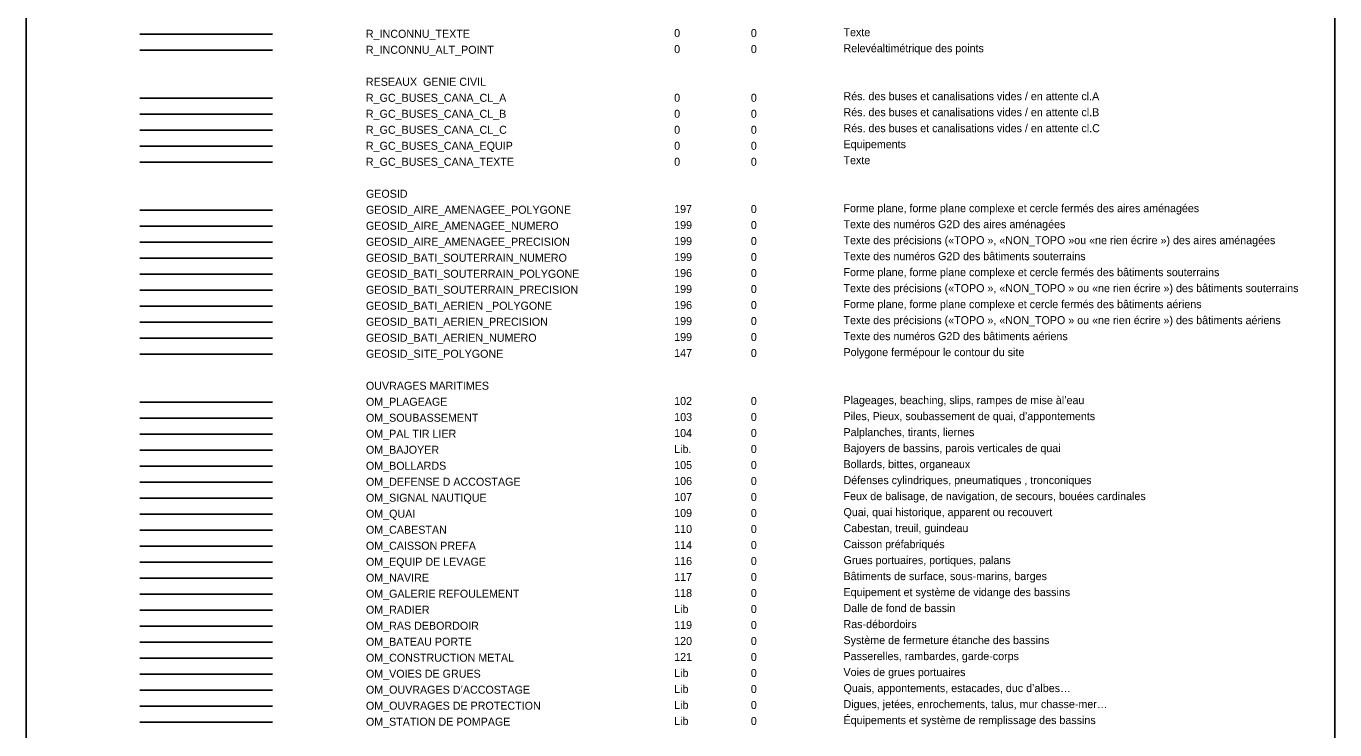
# Model space of a CAD drawing. Extents: x -60 to 214, y -380 to -21.
# Drawn here: x 33.1 to 114.8, y -334.9 to -290.9 of the extents above; entities that cross this region are included whole.
import ezdxf

# ---------------------------------------------------------------- set-up
doc = ezdxf.new("R2010")
doc.units = 0
for name, color, linetype in [('Default', 7, 'Continuous'), ('DH_TEXTE', 7, 'Continuous'), ('GEOSID_AIRE_AMENAGEE_NUMERO', 7, 'Continuous'), ('GEOSID_AIRE_AMENAGEE_POLYGONE', 7, 'Continuous'), ('GEOSID_AIRE_AMENAGEE_PRECISION', 7, 'Continuous'), ('GEOSID_BATI_AERIEN _POLYGONE', 7, 'Continuous'), ('GEOSID_BATI_AERIEN_NUMERO', 7, 'Continuous'), ('GEOSID_BATI_AERIEN_PRECISION', 7, 'Continuous'), ('GEOSID_BATI_SOUTERRAIN_NUMERO', 7, 'Continuous'), ('GEOSID_BATI_SOUTERRAIN_POLYGONE', 7, 'Continuous'), ('GEOSID_BATI_SOUTERRAIN_PRECISION', 7, 'Continuous'), ('GEOSID_SITE_POLYGONE', 7, 'Continuous'), ('OM_BAJOYER', 7, 'Continuous'), ('OM_BATEAU PORTE', 7, 'Continuous'), ('OM_BOLLARDS', 7, 'Continuous'), ('OM_CABESTAN', 7, 'Continuous'), ('OM_CAISSON PREFA', 7, 'Continuous'), ('OM_CONSTRUCTION METAL', 7, 'Continuous'), ('OM_DEFENSE D ACCOSTAGE', 7, 'Continuous'), ('OM_EQUIP DE LEVAGE', 7, 'Continuous'), ('OM_GALERIE REFOULEMENT', 7, 'Continuous'), ('OM_NAVIRE', 7, 'Continuous'), ('OM_OUVRAGES DE PROTECTION', 7, 'Continuous'), ('OM_OUVRAGES D’ACCOSTAGE', 7, 'Continuous'), ('OM_PAL TIR LIER', 7, 'Continuous'), ('OM_PLAGEAGE', 7, 'Continuous'), ('OM_QUAI', 7, 'Continuous'), ('OM_RADIER', 7, 'Continuous'), ('OM_RAS DEBORDOIR', 7, 'Continuous'), ('OM_SIGNAL NAUTIQUE', 7, 'Continuous'), ('OM_SOUBASSEMENT', 7, 'Continuous'), ('OM_STATION DE POMPAGE', 7, 'Continuous'), ('OM_VOIES DE GRUES', 7, 'Continuous'), ('R_GC_BUSES_CANA_CL_A', 7, 'Continuous'), ('R_GC_BUSES_CANA_CL_B', 7, 'Continuous'), ('R_GC_BUSES_CANA_CL_C', 7, 'Continuous'), ('R_GC_BUSES_CANA_EQUIP', 7, 'Continuous'), ('R_GC_BUSES_CANA_TEXTE', 7, 'Continuous'), ('R_INCONNU_ALT_POINT', 7, 'Continuous'), ('R_INCONNU_TEXTE', 7, 'Continuous')]:
    doc.layers.add(name, color=color, linetype=linetype)

msp = doc.modelspace()

# ---------------------------------------------------------------- linework, layer by layer
at = {"layer": 'Default'}
msp.add_lwpolyline([(114.838, -25.727), (33.073, -25.727), (33.073, -380.216), (114.838, -380.216)], close=True, dxfattribs=at)
at = {"layer": 'GEOSID_AIRE_AMENAGEE_NUMERO'}
msp.add_line((40.178, -303.429), (48.457, -303.429), dxfattribs=at)
at = {"layer": 'GEOSID_AIRE_AMENAGEE_POLYGONE'}
msp.add_line((40.178, -302.429), (48.457, -302.429), dxfattribs=at)
at = {"layer": 'GEOSID_AIRE_AMENAGEE_PRECISION'}
msp.add_line((40.178, -304.429), (48.457, -304.429), dxfattribs=at)
at = {"layer": 'GEOSID_BATI_AERIEN _POLYGONE'}
msp.add_line((40.178, -308.429), (48.457, -308.429), dxfattribs=at)
at = {"layer": 'GEOSID_BATI_AERIEN_NUMERO'}
msp.add_line((40.178, -310.429), (48.457, -310.429), dxfattribs=at)
at = {"layer": 'GEOSID_BATI_AERIEN_PRECISION'}
msp.add_line((40.178, -309.429), (48.457, -309.429), dxfattribs=at)
at = {"layer": 'GEOSID_BATI_SOUTERRAIN_NUMERO'}
msp.add_line((40.178, -305.429), (48.457, -305.429), dxfattribs=at)
at = {"layer": 'GEOSID_BATI_SOUTERRAIN_POLYGONE'}
msp.add_line((40.178, -306.429), (48.457, -306.429), dxfattribs=at)
at = {"layer": 'GEOSID_BATI_SOUTERRAIN_PRECISION'}
msp.add_line((40.178, -307.429), (48.457, -307.429), dxfattribs=at)
at = {"layer": 'GEOSID_SITE_POLYGONE'}
msp.add_line((40.178, -311.429), (48.457, -311.429), dxfattribs=at)
at = {"layer": 'OM_BAJOYER'}
msp.add_line((40.178, -317.429), (48.457, -317.429), dxfattribs=at)
at = {"layer": 'OM_BATEAU PORTE'}
msp.add_line((40.178, -329.429), (48.457, -329.429), dxfattribs=at)
at = {"layer": 'OM_BOLLARDS'}
msp.add_line((40.178, -318.429), (48.457, -318.429), dxfattribs=at)
at = {"layer": 'OM_CABESTAN'}
msp.add_line((40.178, -322.429), (48.457, -322.429), dxfattribs=at)
at = {"layer": 'OM_CAISSON PREFA'}
msp.add_line((40.178, -323.429), (48.457, -323.429), dxfattribs=at)
at = {"layer": 'OM_CONSTRUCTION METAL'}
msp.add_line((40.178, -330.429), (48.457, -330.429), dxfattribs=at)
at = {"layer": 'OM_DEFENSE D ACCOSTAGE'}
msp.add_line((40.178, -319.429), (48.457, -319.429), dxfattribs=at)
at = {"layer": 'OM_EQUIP DE LEVAGE'}
msp.add_line((40.178, -324.429), (48.457, -324.429), dxfattribs=at)
at = {"layer": 'OM_GALERIE REFOULEMENT'}
msp.add_line((40.178, -326.429), (48.457, -326.429), dxfattribs=at)
at = {"layer": 'OM_NAVIRE'}
msp.add_line((40.178, -325.429), (48.457, -325.429), dxfattribs=at)
at = {"layer": 'OM_OUVRAGES DE PROTECTION'}
msp.add_line((40.178, -333.429), (48.457, -333.429), dxfattribs=at)
at = {"layer": 'OM_OUVRAGES D’ACCOSTAGE'}
msp.add_line((40.178, -332.429), (48.457, -332.429), dxfattribs=at)
at = {"layer": 'OM_PAL TIR LIER'}
msp.add_line((40.178, -316.429), (48.457, -316.429), dxfattribs=at)
at = {"layer": 'OM_PLAGEAGE'}
msp.add_line((40.178, -314.429), (48.457, -314.429), dxfattribs=at)
at = {"layer": 'OM_QUAI'}
msp.add_line((40.178, -321.429), (48.457, -321.429), dxfattribs=at)
at = {"layer": 'OM_RADIER'}
msp.add_line((40.178, -327.429), (48.457, -327.429), dxfattribs=at)
at = {"layer": 'OM_RAS DEBORDOIR'}
msp.add_line((40.178, -328.429), (48.457, -328.429), dxfattribs=at)
at = {"layer": 'OM_SIGNAL NAUTIQUE'}
msp.add_line((40.178, -320.429), (48.457, -320.429), dxfattribs=at)
at = {"layer": 'OM_SOUBASSEMENT'}
msp.add_line((40.178, -315.429), (48.457, -315.429), dxfattribs=at)
at = {"layer": 'OM_STATION DE POMPAGE'}
msp.add_line((40.178, -334.429), (48.457, -334.429), dxfattribs=at)
at = {"layer": 'OM_VOIES DE GRUES'}
msp.add_line((40.178, -331.429), (48.457, -331.429), dxfattribs=at)
at = {"layer": 'R_GC_BUSES_CANA_CL_A'}
msp.add_line((40.178, -295.429), (48.457, -295.429), dxfattribs=at)
at = {"layer": 'R_GC_BUSES_CANA_CL_B'}
msp.add_line((40.178, -296.429), (48.457, -296.429), dxfattribs=at)
at = {"layer": 'R_GC_BUSES_CANA_CL_C'}
msp.add_line((40.178, -297.429), (48.457, -297.429), dxfattribs=at)
at = {"layer": 'R_GC_BUSES_CANA_EQUIP'}
msp.add_line((40.178, -298.429), (48.457, -298.429), dxfattribs=at)
at = {"layer": 'R_GC_BUSES_CANA_TEXTE'}
msp.add_line((40.178, -299.429), (48.457, -299.429), dxfattribs=at)
at = {"layer": 'R_INCONNU_ALT_POINT'}
msp.add_line((40.178, -292.429), (48.457, -292.429), dxfattribs=at)
at = {"layer": 'R_INCONNU_TEXTE'}
msp.add_line((40.178, -291.429), (48.457, -291.429), dxfattribs=at)

# ---------------------------------------------------------------- texts
at = {"layer": 'DH_TEXTE'}
for s, p in [('RESEAUX  GENIE CIVIL', (54.301, -294.655)), ('GEOSID ', (54.301, -301.655)), ('OUVRAGES MARITIMES ', (54.301, -313.655))]:
    msp.add_text(s, height=0.5, dxfattribs=at).set_placement(p)
at = {"layer": 'GEOSID_AIRE_AMENAGEE_NUMERO'}
for s, p in [('GEOSID_AIRE_AMENAGEE_NUMERO ', (54.301, -303.655)), ('199 ', (73.561, -303.61)), ('0 ', (78.351, -303.61)), ('Texte des numéros G2D des aires aménagées ', (84.14, -303.555))]:
    msp.add_text(s, height=0.5, dxfattribs=at).set_placement(p)
at = {"layer": 'GEOSID_AIRE_AMENAGEE_POLYGONE'}
for s, p in [('GEOSID_AIRE_AMENAGEE_POLYGONE ', (54.301, -302.655)), ('197 ', (73.559, -302.61)), ('0 ', (78.348, -302.61)), ('Forme plane, forme plane complexe et cercle fermés des aires aménagées ', (84.138, -302.555))]:
    msp.add_text(s, height=0.5, dxfattribs=at).set_placement(p)
at = {"layer": 'GEOSID_AIRE_AMENAGEE_PRECISION'}
for s, p in [('GEOSID_AIRE_AMENAGEE_PRECISION ', (54.301, -304.655)), ('199 ', (73.561, -304.61)), ('0 ', (78.351, -304.61)), ('Texte des précisions («TOPO », «NON_TOPO »ou «ne rien écrire ») des aires aménagées ', (84.14, -304.555))]:
    msp.add_text(s, height=0.5, dxfattribs=at).set_placement(p)
at = {"layer": 'GEOSID_BATI_AERIEN _POLYGONE'}
for s, p in [('GEOSID_BATI_AERIEN _POLYGONE ', (54.301, -308.655)), ('196 ', (73.561, -308.61)), ('0 ', (78.351, -308.61)), ('Forme plane, forme plane complexe et cercle fermés des bâtiments aériens ', (84.14, -308.555))]:
    msp.add_text(s, height=0.5, dxfattribs=at).set_placement(p)
at = {"layer": 'GEOSID_BATI_AERIEN_NUMERO'}
for s, p in [('GEOSID_BATI_AERIEN_NUMERO ', (54.301, -310.655)), ('199 ', (73.561, -310.61)), ('0 ', (78.351, -310.61)), ('Texte des numéros G2D des bâtiments aériens ', (84.14, -310.555))]:
    msp.add_text(s, height=0.5, dxfattribs=at).set_placement(p)
at = {"layer": 'GEOSID_BATI_AERIEN_PRECISION'}
for s, p in [('Texte des précisions («TOPO », «NON_TOPO » ou «ne rien écrire ») des bâtiments aériens ', (84.14, -309.555)), ('GEOSID_BATI_AERIEN_PRECISION ', (54.301, -309.655)), ('199 ', (73.561, -309.61)), ('0 ', (78.351, -309.61))]:
    msp.add_text(s, height=0.5, dxfattribs=at).set_placement(p)
at = {"layer": 'GEOSID_BATI_SOUTERRAIN_NUMERO'}
for s, p in [('GEOSID_BATI_SOUTERRAIN_NUMERO ', (54.301, -305.655)), ('199 ', (73.561, -305.61)), ('0 ', (78.351, -305.61)), ('Texte des numéros G2D des bâtiments souterrains ', (84.14, -305.555))]:
    msp.add_text(s, height=0.5, dxfattribs=at).set_placement(p)
at = {"layer": 'GEOSID_BATI_SOUTERRAIN_POLYGONE'}
for s, p in [('GEOSID_BATI_SOUTERRAIN_POLYGONE ', (54.301, -306.655)), ('196 ', (73.561, -306.61)), ('0 ', (78.351, -306.61)), ('Forme plane, forme plane complexe et cercle fermés des bâtiments souterrains ', (84.14, -306.555))]:
    msp.add_text(s, height=0.5, dxfattribs=at).set_placement(p)
at = {"layer": 'GEOSID_BATI_SOUTERRAIN_PRECISION'}
for s, p in [('GEOSID_BATI_SOUTERRAIN_PRECISION ', (54.301, -307.655)), ('199 ', (73.561, -307.61)), ('0 ', (78.351, -307.61)), ('Texte des précisions («TOPO », «NON_TOPO » ou «ne rien écrire ») des bâtiments souterrains ', (84.14, -307.555))]:
    msp.add_text(s, height=0.5, dxfattribs=at).set_placement(p)
at = {"layer": 'GEOSID_SITE_POLYGONE'}
for s, p in [('GEOSID_SITE_POLYGONE ', (54.301, -311.655)), ('147 ', (73.561, -311.61)), ('0 ', (78.351, -311.61)), ('Polygone fermépour le contour du site ', (84.14, -311.555))]:
    msp.add_text(s, height=0.5, dxfattribs=at).set_placement(p)
at = {"layer": 'OM_BAJOYER'}
for s, p in [('OM_BAJOYER ', (54.301, -317.655)), ('Lib. ', (73.561, -317.61)), ('0', (78.348, -317.61)), ('Bajoyers de bassins, parois verticales de quai ', (84.14, -317.555))]:
    msp.add_text(s, height=0.5, dxfattribs=at).set_placement(p)
at = {"layer": 'OM_BATEAU PORTE'}
for s, p in [('OM_BATEAU PORTE ', (54.301, -329.655)), ('120 ', (73.561, -329.61)), ('0', (78.348, -329.61)), ('Système de fermeture étanche des bassins ', (84.14, -329.555))]:
    msp.add_text(s, height=0.5, dxfattribs=at).set_placement(p)
at = {"layer": 'OM_BOLLARDS'}
for s, p in [('Bollards, bittes, organeaux ', (84.14, -318.555)), ('OM_BOLLARDS ', (54.301, -318.655)), ('105 ', (73.561, -318.61)), ('0', (78.348, -318.61))]:
    msp.add_text(s, height=0.5, dxfattribs=at).set_placement(p)
at = {"layer": 'OM_CABESTAN'}
for s, p in [('OM_CABESTAN ', (54.301, -322.655)), ('110 ', (73.561, -322.61)), ('0', (78.348, -322.61)), ('Cabestan, treuil, guindeau ', (84.14, -322.555))]:
    msp.add_text(s, height=0.5, dxfattribs=at).set_placement(p)
at = {"layer": 'OM_CAISSON PREFA'}
for s, p in [('OM_CAISSON PREFA ', (54.301, -323.655)), ('114 ', (73.561, -323.61)), ('0', (78.348, -323.61)), ('Caisson préfabriqués ', (84.14, -323.555))]:
    msp.add_text(s, height=0.5, dxfattribs=at).set_placement(p)
at = {"layer": 'OM_CONSTRUCTION METAL'}
for s, p in [('OM_CONSTRUCTION METAL ', (54.301, -330.655)), ('121 ', (73.561, -330.61)), ('0', (78.348, -330.61)), ('Passerelles, rambardes, garde-corps ', (84.14, -330.555))]:
    msp.add_text(s, height=0.5, dxfattribs=at).set_placement(p)
at = {"layer": 'OM_DEFENSE D ACCOSTAGE'}
for s, p in [('OM_DEFENSE D ACCOSTAGE ', (54.301, -319.655)), ('106 ', (73.561, -319.61)), ('0', (78.348, -319.61)), ('Défenses cylindriques, pneumatiques , tronconiques ', (84.14, -319.555))]:
    msp.add_text(s, height=0.5, dxfattribs=at).set_placement(p)
at = {"layer": 'OM_EQUIP DE LEVAGE'}
for s, p in [('OM_EQUIP DE LEVAGE ', (54.301, -324.655)), ('116 ', (73.561, -324.61)), ('0', (78.348, -324.61)), ('Grues portuaires, portiques, palans ', (84.14, -324.555))]:
    msp.add_text(s, height=0.5, dxfattribs=at).set_placement(p)
at = {"layer": 'OM_GALERIE REFOULEMENT'}
for s, p in [('OM_GALERIE REFOULEMENT ', (54.301, -326.655)), ('118 ', (73.561, -326.61)), ('0', (78.348, -326.61)), ('Equipement et système de vidange des bassins ', (84.14, -326.555))]:
    msp.add_text(s, height=0.5, dxfattribs=at).set_placement(p)
at = {"layer": 'OM_NAVIRE'}
for s, p in [('OM_NAVIRE ', (54.301, -325.655)), ('117 ', (73.561, -325.61)), ('0', (78.348, -325.61)), ('Bâtiments de surface, sous-marins, barges ', (84.14, -325.555))]:
    msp.add_text(s, height=0.5, dxfattribs=at).set_placement(p)
at = {"layer": 'OM_OUVRAGES DE PROTECTION'}
for s, p in [('OM_OUVRAGES DE PROTECTION ', (54.301, -333.655)), ('Lib ', (73.561, -333.61)), ('0', (78.348, -333.61)), ('Digues, jetées, enrochements, talus, mur chasse-mer…', (84.14, -333.555))]:
    msp.add_text(s, height=0.5, dxfattribs=at).set_placement(p)
at = {"layer": 'OM_OUVRAGES D’ACCOSTAGE'}
for s, p in [('OM_OUVRAGES D’ACCOSTAGE ', (54.301, -332.655)), ('Lib ', (73.561, -332.61)), ('0', (78.348, -332.61)), ('Quais, appontements, estacades, duc d’albes…', (84.14, -332.555))]:
    msp.add_text(s, height=0.5, dxfattribs=at).set_placement(p)
at = {"layer": 'OM_PAL TIR LIER'}
for s, p in [('OM_PAL TIR LIER ', (54.301, -316.655)), ('104 ', (73.561, -316.61)), ('0', (78.348, -316.61)), ('Palplanches, tirants, liernes ', (84.14, -316.555))]:
    msp.add_text(s, height=0.5, dxfattribs=at).set_placement(p)
at = {"layer": 'OM_PLAGEAGE'}
for s, p in [('OM_PLAGEAGE ', (54.301, -314.655)), ('102 ', (73.559, -314.61)), ('0', (78.348, -314.61)), ('Plageages, beaching, slips, rampes de mise àl’eau ', (84.138, -314.555))]:
    msp.add_text(s, height=0.5, dxfattribs=at).set_placement(p)
at = {"layer": 'OM_QUAI'}
for s, p in [('OM_QUAI ', (54.301, -321.655)), ('109 ', (73.561, -321.61)), ('0', (78.348, -321.61)), ('Quai, quai historique, apparent ou recouvert ', (84.14, -321.555))]:
    msp.add_text(s, height=0.5, dxfattribs=at).set_placement(p)
at = {"layer": 'OM_RADIER'}
for s, p in [('Dalle de fond de bassin ', (84.14, -327.555)), ('OM_RADIER ', (54.301, -327.655)), ('Lib ', (73.561, -327.61)), ('0', (78.348, -327.61))]:
    msp.add_text(s, height=0.5, dxfattribs=at).set_placement(p)
at = {"layer": 'OM_RAS DEBORDOIR'}
for s, p in [('OM_RAS DEBORDOIR ', (54.301, -328.655)), ('119 ', (73.561, -328.61)), ('0', (78.348, -328.61)), ('Ras-débordoirs ', (84.14, -328.555))]:
    msp.add_text(s, height=0.5, dxfattribs=at).set_placement(p)
at = {"layer": 'OM_SIGNAL NAUTIQUE'}
for s, p in [('OM_SIGNAL NAUTIQUE ', (54.301, -320.655)), ('107 ', (73.561, -320.61)), ('0', (78.348, -320.61)), ('Feux de balisage, de navigation, de secours, bouées cardinales ', (84.14, -320.555))]:
    msp.add_text(s, height=0.5, dxfattribs=at).set_placement(p)
at = {"layer": 'OM_SOUBASSEMENT'}
for s, p in [('OM_SOUBASSEMENT ', (54.301, -315.655)), ('103 ', (73.561, -315.61)), ('0', (78.348, -315.61)), ('Piles, Pieux, soubassement de quai, d’appontements ', (84.14, -315.555))]:
    msp.add_text(s, height=0.5, dxfattribs=at).set_placement(p)
at = {"layer": 'OM_STATION DE POMPAGE'}
for s, p in [('OM_STATION DE POMPAGE  ', (54.301, -334.655)), ('Lib ', (73.561, -334.61)), ('0', (78.348, -334.61)), ('Équipements et système de remplissage des bassins ', (84.14, -334.555))]:
    msp.add_text(s, height=0.5, dxfattribs=at).set_placement(p)
at = {"layer": 'OM_VOIES DE GRUES'}
for s, p in [('OM_VOIES DE GRUES ', (54.301, -331.655)), ('Lib ', (73.561, -331.61)), ('0', (78.348, -331.61)), ('Voies de grues portuaires ', (84.14, -331.555))]:
    msp.add_text(s, height=0.5, dxfattribs=at).set_placement(p)
at = {"layer": 'R_GC_BUSES_CANA_CL_A'}
for s, p in [('R_GC_BUSES_CANA_CL_A ', (54.301, -295.655)), ('Rés. des buses et canalisations vides / en attente cl.A ', (84.138, -295.555))]:
    msp.add_text(s, height=0.5, dxfattribs=at).set_placement(p)
at = {"layer": 'R_GC_BUSES_CANA_CL_B'}
for s, p in [('R_GC_BUSES_CANA_CL_B ', (54.301, -296.655)), ('Rés. des buses et canalisations vides / en attente cl.B ', (84.14, -296.555))]:
    msp.add_text(s, height=0.5, dxfattribs=at).set_placement(p)
at = {"layer": 'R_GC_BUSES_CANA_CL_C'}
for s, p in [('R_GC_BUSES_CANA_CL_C ', (54.301, -297.655)), ('Rés. des buses et canalisations vides / en attente cl.C ', (84.14, -297.555))]:
    msp.add_text(s, height=0.5, dxfattribs=at).set_placement(p)
at = {"layer": 'R_GC_BUSES_CANA_EQUIP'}
for s, p in [('R_GC_BUSES_CANA_EQUIP ', (54.301, -298.655)), ('Equipements ', (84.14, -298.555))]:
    msp.add_text(s, height=0.5, dxfattribs=at).set_placement(p)
at = {"layer": 'R_GC_BUSES_CANA_TEXTE'}
for s, p in [('R_GC_BUSES_CANA_TEXTE ', (54.301, -299.655)), ('Texte ', (84.14, -299.555))]:
    msp.add_text(s, height=0.5, dxfattribs=at).set_placement(p)
at = {"layer": 'R_INCONNU_ALT_POINT'}
for s, p in [('R_INCONNU_ALT_POINT  ', (54.301, -292.655)), ('0 ', (73.561, -292.61)), ('0 ', (78.351, -292.61)), ('Relevéaltimétrique des points ', (84.14, -292.555)), ('0 ', (73.561, -295.655)), ('0 ', (78.351, -295.655)), ('0 ', (73.561, -296.655)), ('0 ', (78.351, -296.655)), ('0 ', (73.561, -297.655)), ('0 ', (78.351, -297.655)), ('0 ', (73.561, -298.655)), ('0 ', (78.351, -298.655)), ('0 ', (73.561, -299.655)), ('0 ', (78.351, -299.655))]:
    msp.add_text(s, height=0.5, dxfattribs=at).set_placement(p)
at = {"layer": 'R_INCONNU_TEXTE'}
for s, p in [('Texte ', (84.14, -291.555)), ('R_INCONNU_TEXTE ', (54.301, -291.655)), ('0', (73.561, -291.61)), ('0 ', (78.351, -291.61))]:
    msp.add_text(s, height=0.5, dxfattribs=at).set_placement(p)

doc.saveas('drawing.dxf')
